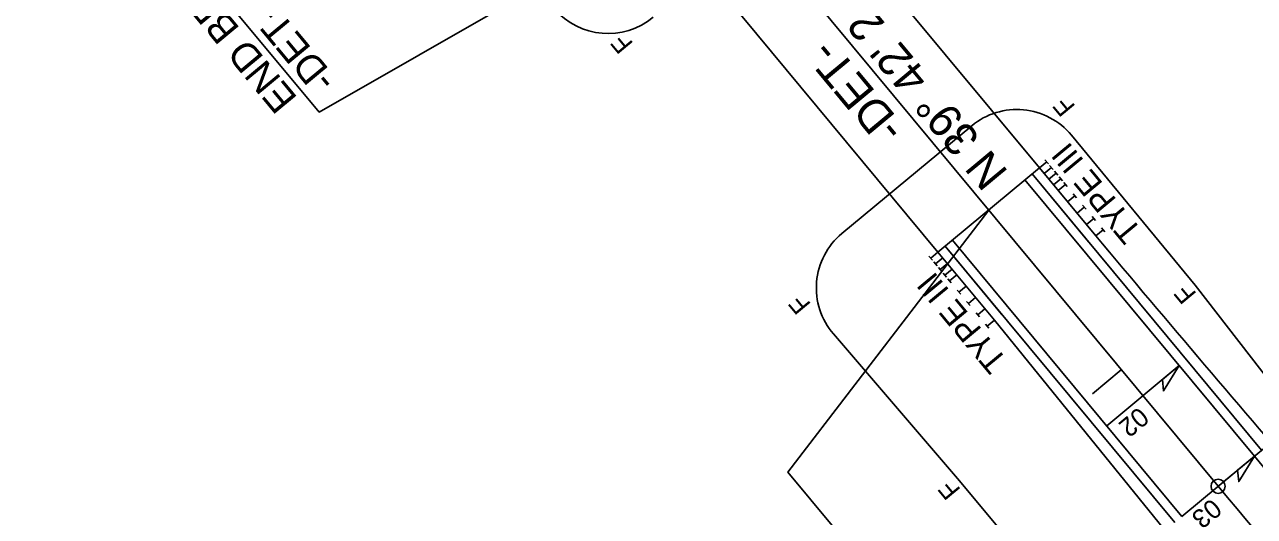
# Model space of a CAD drawing. Extents: x 2597390 to 2598563, y 852595 to 853909.
# Drawn here: x 2597808.1 to 2598069.2, y 853159.2 to 853263.6 of the extents above; entities that cross this region are included whole.
import ezdxf

# ---------------------------------------------------------------- set-up
doc = ezdxf.new("R2010")
doc.units = 0
for name, color, linetype in [('Prop DSN Text', 7, 'Continuous'), ('Prop EOT', 7, 'Continuous'), ('Prop Guardrail', 7, 'Continuous'), ('Prop Guardrail Temporary', 7, 'Continuous'), ('Prop Horizontal Alignment', 7, 'Continuous'), ('Prop Horizontal Alignment Direction Label', 7, 'Continuous'), ('Prop Horizontal Alignment Station Label', 7, 'Continuous'), ('Prop Horizontal Alignment Tick Large', 7, 'Continuous'), ('Prop Paved Shoulder', 7, 'Continuous'), ('Prop Roadway Bridge', 7, 'Continuous'), ('Prop SS Fill Line', 7, 'Continuous'), ('Prop SS Misc', 7, 'Continuous'), ('Prop Structure Anchor Unit CELL', 7, 'Continuous'), ('Prop Superelevation  Arrow CELL', 7, 'Continuous'), ('Prop Superelevation Label', 7, 'Continuous')]:
    doc.layers.add(name, color=color, linetype=linetype)

msp = doc.modelspace()

# ---------------------------------------------------------------- linework, layer by layer
at = {"layer": 'Prop DSN Text'}
for points in [[(2597955.29, 853293.48), (2597870.68, 853245.02), (2597808.12, 853320.2)], [(2598032.88, 853093.04), (2597970.16, 853168.56), (2598012.79, 853224.24)]]:
    msp.add_lwpolyline(points, dxfattribs=at)
at = {"layer": 'Prop EOT'}
for p, q in [((2598069.2, 853171.97), (2598020.48, 853230.63)), ((2598053.81, 853159.19), (2598005.1, 853217.85))]:
    msp.add_line(p, q, dxfattribs=at)
msp.add_arc((2598702.35, 853697.75), 823, 219.70669, 233.47068, dxfattribs=at)
at = {"layer": 'Prop Guardrail'}
for p, q in [((2598034, 853217.48), (2598022.02, 853231.9)), ((2598015.54, 853202.15), (2598003.56, 853216.57))]:
    msp.add_line(p, q, dxfattribs=at)
at = {"layer": 'Prop Guardrail Temporary'}
for p, q in [((2598035.54, 853218.76), (2598023.56, 853233.18)), ((2598014, 853200.87), (2598002.02, 853215.29)), ((2598014, 853200.87), (2598050.83, 853155.47))]:
    msp.add_line(p, q, dxfattribs=at)
msp.add_arc((2601230.03, 855890.15), 4164.27, 219.90413, 220.88881, dxfattribs=at)
at = {"layer": 'Prop Horizontal Alignment'}
msp.add_line((2598061.5, 853165.58), (2597930.04, 853323.88), dxfattribs=at)
msp.add_arc((2598702.35, 853697.75), 833, 219.70669, 233.47068, dxfattribs=at)
at = {"layer": 'Prop Horizontal Alignment Station Label'}
msp.add_line((2598062.66, 853166.54), (2598250.11, 853322.2), dxfattribs=at)
msp.add_circle((2598061.5, 853165.58), 1.5, dxfattribs=at)
at = {"layer": 'Prop Horizontal Alignment Tick Large'}
msp.add_line((2598040.94, 853190.34), (2598034.79, 853185.23), dxfattribs=at)
at = {"layer": 'Prop Paved Shoulder'}
for p, q in [((2598070.73, 853173.24), (2598022.02, 853231.9)), ((2598052.27, 853157.91), (2598003.56, 853216.57))]:
    msp.add_line(p, q, dxfattribs=at)
at = {"layer": 'Prop Roadway Bridge'}
for p, q in [((2598023.56, 853233.18), (2597966.06, 853302.42)), ((2598002.02, 853215.29), (2597944.52, 853284.53)), ((2598023.56, 853233.18), (2598002.02, 853215.29))]:
    msp.add_line(p, q, dxfattribs=at)
at = {"layer": 'Prop SS Fill Line'}
for p, q in [((2597981.61, 853219.23), (2598009.19, 853242.13)), ((2598056.63, 853208.32), (2598030.34, 853240.15)), ((2598087.2, 853168.72), (2598056.63, 853208.32)), ((2598006.57, 853166.75), (2597979.81, 853197.93)), ((2598038.59, 853128.35), (2598006.57, 853166.75))]:
    msp.add_line(p, q, dxfattribs=at)
for centre, start, end in [((2597931.96, 853276.72), 220.6358, 309.7067), ((2598018.77, 853230.59), 39.5631, 129.7067), ((2597991.2, 853207.69), 129.7067, 220.6358)]:
    msp.add_arc(centre, 15, start, end, dxfattribs=at)
at = {"layer": 'Prop Structure Anchor Unit CELL'}
for p, q in [((2598023.56, 853233.18), (2598025.1, 853234.46)), ((2598023.56, 853233.18), (2598035.54, 853218.76)), ((2598024.56, 853231.98), (2598026.1, 853233.26)), ((2598024.73, 853234.9), (2598025.47, 853234.02)), ((2598025.73, 853233.7), (2598026.46, 853232.82)), ((2598025.56, 853230.78), (2598027.1, 853232.06)), ((2598026.56, 853229.58), (2598028.09, 853230.85)), ((2598026.73, 853232.5), (2598027.46, 853231.62)), ((2598027.73, 853231.29), (2598028.46, 853230.41)), ((2598027.55, 853228.37), (2598029.09, 853229.65)), ((2598028.73, 853230.09), (2598029.46, 853229.21)), ((2598030.72, 853227.69), (2598031.45, 853226.81)), ((2598029.55, 853225.97), (2598031.09, 853227.25)), ((2598032.72, 853225.28), (2598033.45, 853224.4)), ((2598031.55, 853223.57), (2598033.08, 853224.84)), ((2598033.54, 853221.16), (2598035.08, 853222.44)), ((2598034.72, 853222.88), (2598035.45, 853222)), ((2598035.54, 853218.76), (2598037.08, 853220.04)), ((2598036.71, 853220.48), (2598037.44, 853219.59)), ((2598002.02, 853215.29), (2598000.48, 853214.02)), ((2598002.02, 853215.29), (2598014, 853200.87)), ((2598000.11, 853214.46), (2598000.85, 853213.58)), ((2598001.11, 853213.26), (2598001.84, 853212.37)), ((2598003.02, 853214.09), (2598001.48, 853212.81)), ((2598002.11, 853212.05), (2598002.84, 853211.17)), ((2598004.02, 853212.89), (2598002.48, 853211.61)), ((2598003.11, 853210.85), (2598003.84, 853209.97)), ((2598005.01, 853211.69), (2598003.48, 853210.41)), ((2598004.11, 853209.65), (2598004.84, 853208.77)), ((2598006.01, 853210.49), (2598004.47, 853209.21)), ((2598006.1, 853207.25), (2598006.84, 853206.36)), ((2598008.01, 853208.08), (2598006.47, 853206.8)), ((2598008.1, 853204.84), (2598008.83, 853203.96)), ((2598010.01, 853205.68), (2598008.47, 853204.4)), ((2598010.1, 853202.44), (2598010.83, 853201.56)), ((2598012, 853203.27), (2598010.46, 853202)), ((2598012.09, 853200.03), (2598012.83, 853199.15)), ((2598014, 853200.87), (2598012.46, 853199.59))]:
    msp.add_line(p, q, dxfattribs=at)
at = {"layer": 'Prop Superelevation  Arrow CELL'}
for points in [[(2598053.22, 853191.2), (2598049.89, 853185.83), (2598049.67, 853188.25)], [(2598069.2, 853171.97), (2598065.86, 853166.6), (2598065.64, 853169.01)]]:
    msp.add_lwpolyline(points, close=True, dxfattribs=at)
at = {"layer": 'Prop Superelevation Label'}
for p, q in [((2598037.84, 853178.42), (2598053.22, 853191.2)), ((2598069.2, 853171.97), (2598053.81, 853159.19))]:
    msp.add_line(p, q, dxfattribs=at)

# ---------------------------------------------------------------- texts
at = {"layer": 'Prop DSN Text'}
for s, p in [('-DET- POT 16+34.06', (2597874.57, 853252.04)), (' END BRIDGE', (2597867.65, 853246.29))]:
    msp.add_text(s, height=6, rotation=129.7066, dxfattribs=at).set_placement(p)
at = {"layer": 'Prop Horizontal Alignment Direction Label'}
for s, p in [('N 39%%d 42\' 24.1" W', (2598017.13, 853232.29)), ('-DET-', (2597995.23, 853241.71))]:
    msp.add_text(s, height=7, rotation=129.7067, dxfattribs=at).set_placement(p)
at = {"layer": 'Prop SS Misc'}
for p in [(2597937.48, 853259.58), (2598031.35, 853246.24), (2598057.07, 853206.44), (2597975.22, 853204.23), (2598006.99, 853164.85)]:
    msp.add_text('F', height=4, rotation=129.7067, dxfattribs=at).set_placement(p)
at = {"layer": 'Prop Structure Anchor Unit CELL'}
for p in [(2598045.54, 853219.82), (2598016.96, 853192.26)]:
    msp.add_text('TYPE III', height=5, rotation=129.7067, dxfattribs=at).set_placement(p)
at = {"layer": 'Prop Superelevation Label'}
for s, p in [('02', (2598044.65, 853182.61)), ('03', (2598060.12, 853163.2))]:
    msp.add_text(s, height=4, rotation=219.7067, dxfattribs=at).set_placement(p)

doc.saveas('drawing.dxf')
